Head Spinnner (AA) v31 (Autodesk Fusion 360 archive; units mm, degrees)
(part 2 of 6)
sketch "Driven Gear Hole for Z Restric." plane through (0, 0, 31.75) normal (0, 0, -1) x axis (1, 0, 0)
  line L1 (10.4441, 8.6506) -> (10.3664, 8.5861)
  curve K1 (11.5764, 10.8628) -> (10.4441, 8.6506)
  curve K2 (10.8676, 11.5719) -> (8.655, 10.4405)
  line L2 (8.5904, 10.3628) -> (8.655, 10.4405)
  line L3 (7.2598, 11.4546) -> (7.2058, 11.3693)
  curve K3 (7.6531, 13.9084) -> (7.2598, 11.4546)
  curve K4 (6.7598, 14.3638) -> (5.0051, 12.604)
  line L4 (4.9677, 12.5102) -> (5.0051, 12.604)
  line L5 (3.3648, 13.1374) -> (3.3398, 13.0395)
  curve K5 (2.9806, 15.5926) -> (3.3648, 13.1374)
  curve K6 (1.9903, 15.7497) -> (0.8652, 13.5338)
  line L6 (0.8587, 13.433) -> (0.8652, 13.5338)
  line L7 (-0.8596, 13.5342) -> (-0.8531, 13.4334)
  curve K7 (-1.9837, 15.7505) -> (-0.8596, 13.5342)
  curve K8 (-2.9741, 15.5939) -> (-3.3593, 13.1388)
  line L8 (-3.3344, 13.0409) -> (-3.3593, 13.1388)
  line L9 (-4.9998, 12.6061) -> (-4.9625, 12.5123)
  curve K9 (-6.7538, 14.3666) -> (-4.9998, 12.6061)
  curve K10 (-7.6473, 13.9116) -> (-7.255, 11.4576)
  line L10 (-7.201, 11.3723) -> (-7.255, 11.4576)
  line L11 (-8.6506, 10.4441) -> (-8.5861, 10.3664)
  curve K11 (-10.8628, 11.5764) -> (-8.6506, 10.4441)
  curve K12 (-11.5719, 10.8676) -> (-10.4405, 8.655)
  line L12 (-10.3628, 8.5904) -> (-10.4405, 8.655)
  line L13 (-11.4546, 7.2598) -> (-11.3693, 7.2058)
  curve K13 (-13.9084, 7.6531) -> (-11.4546, 7.2598)
  curve K14 (-14.3638, 6.7598) -> (-12.604, 5.0051)
  line L14 (-12.5102, 4.9677) -> (-12.604, 5.0051)
  line L15 (-13.1374, 3.3648) -> (-13.0395, 3.3398)
  curve K15 (-15.5926, 2.9806) -> (-13.1374, 3.3648)
  curve K16 (-15.7497, 1.9903) -> (-13.5338, 0.8652)
  line L16 (-13.433, 0.8587) -> (-13.5338, 0.8652)
  line L17 (-13.5342, -0.8596) -> (-13.4334, -0.8531)
  curve K17 (-15.7505, -1.9837) -> (-13.5342, -0.8596)
  curve K18 (-15.5939, -2.9741) -> (-13.1388, -3.3593)
  line L18 (-13.0409, -3.3344) -> (-13.1388, -3.3593)
  line L19 (-12.6061, -4.9998) -> (-12.5123, -4.9625)
  curve K19 (-14.3666, -6.7538) -> (-12.6061, -4.9998)
  curve K20 (-13.9116, -7.6473) -> (-11.4576, -7.255)
  line L20 (-11.3723, -7.201) -> (-11.4576, -7.255)
  line L21 (-10.4441, -8.6506) -> (-10.3664, -8.5861)
  curve K21 (-11.5764, -10.8628) -> (-10.4441, -8.6506)
  curve K22 (-10.8676, -11.5719) -> (-8.655, -10.4405)
  line L22 (-8.5904, -10.3628) -> (-8.655, -10.4405)
  line L23 (-7.2598, -11.4546) -> (-7.2058, -11.3693)
  curve K23 (-7.6531, -13.9084) -> (-7.2598, -11.4546)
  curve K24 (-6.7598, -14.3638) -> (-5.0051, -12.604)
  line L24 (-4.9677, -12.5102) -> (-5.0051, -12.604)
  line L25 (-3.3648, -13.1374) -> (-3.3398, -13.0395)
  curve K25 (-2.9806, -15.5926) -> (-3.3648, -13.1374)
  curve K26 (-1.9903, -15.7497) -> (-0.8652, -13.5338)
  line L26 (-0.8587, -13.433) -> (-0.8652, -13.5338)
  line L27 (0.8596, -13.5342) -> (0.8531, -13.4334)
  curve K27 (1.9837, -15.7505) -> (0.8596, -13.5342)
  curve K28 (2.9741, -15.5939) -> (3.3593, -13.1388)
  line L28 (3.3344, -13.0409) -> (3.3593, -13.1388)
  line L29 (4.9998, -12.6061) -> (4.9625, -12.5123)
  curve K29 (6.7538, -14.3666) -> (4.9998, -12.6061)
  curve K30 (7.6473, -13.9116) -> (7.255, -11.4576)
  line L30 (7.201, -11.3723) -> (7.255, -11.4576)
  line L31 (8.6506, -10.4441) -> (8.5861, -10.3664)
  curve K31 (10.8628, -11.5764) -> (8.6506, -10.4441)
  curve K32 (11.5719, -10.8676) -> (10.4405, -8.655)
  line L32 (10.3628, -8.5904) -> (10.4405, -8.655)
  line L33 (11.4546, -7.2598) -> (11.3693, -7.2058)
  curve K33 (13.9084, -7.6531) -> (11.4546, -7.2598)
  curve K34 (14.3638, -6.7598) -> (12.604, -5.0051)
  line L34 (12.5102, -4.9677) -> (12.604, -5.0051)
  line L35 (13.1374, -3.3648) -> (13.0395, -3.3398)
  curve K35 (15.5926, -2.9806) -> (13.1374, -3.3648)
  curve K36 (15.7497, -1.9903) -> (13.5338, -0.8652)
  line L36 (13.433, -0.8587) -> (13.5338, -0.8652)
  line L37 (13.5342, 0.8596) -> (13.4334, 0.8531)
  curve K37 (15.7505, 1.9837) -> (13.5342, 0.8596)
  curve K38 (15.5939, 2.9741) -> (13.1388, 3.3593)
  line L38 (13.0409, 3.3344) -> (13.1388, 3.3593)
  line L39 (12.6061, 4.9998) -> (12.5123, 4.9625)
  curve K39 (14.3666, 6.7538) -> (12.6061, 4.9998)
  curve K40 (13.9116, 7.6473) -> (11.4576, 7.255)
  line L40 (11.3723, 7.201) -> (11.4576, 7.255)
  circle C1 centre (0, 0) radius 3.175
  arc A1 centre (10.9017, 7.9411) radius 0.8382 clockwise from (10.2242, 7.4476) to (10.3664, 8.5861)
  arc A2 centre (0, 0) radius 15.8749 clockwise from (10.8676, 11.5719) to (11.5764, 10.8628)
  arc A3 centre (7.9457, 10.8984) radius 0.8382 clockwise from (8.5904, 10.3628) to (7.4519, 10.2211)
  arc A4 centre (0, 0) radius 12.6492 clockwise from (7.4224, 10.2425) to (7.4519, 10.2211)
  arc A5 centre (7.9142, 10.9213) radius 0.8382 clockwise from (7.4224, 10.2425) to (7.2058, 11.3693)
  arc A6 centre (0, 0) radius 15.8749 clockwise from (6.7598, 14.3638) to (7.6531, 13.9084)
  arc A7 centre (4.189, 12.8204) radius 0.8382 clockwise from (4.9677, 12.5102) to (3.9286, 12.0236)
  arc A8 centre (0, 0) radius 12.6492 clockwise from (3.894, 12.0349) to (3.9286, 12.0236)
  arc A9 centre (4.152, 12.8324) radius 0.8382 clockwise from (3.894, 12.0349) to (3.3398, 13.0395)
  arc A10 centre (0, 0) radius 15.8749 clockwise from (1.9903, 15.7497) to (2.9806, 15.5926)
  arc A11 centre (0.0222, 13.4873) radius 0.8382 clockwise from (0.8587, 13.433) to (0.0209, 12.6491)
  arc A12 centre (0, 0) radius 12.6492 clockwise from (-0.0156, 12.6491) to (0.0209, 12.6491)
  arc A13 centre (-0.0166, 13.4873) radius 0.8382 clockwise from (-0.0156, 12.6491) to (-0.8531, 13.4334)
  arc A14 centre (0, 0) radius 15.8749 clockwise from (-2.9741, 15.5939) to (-1.9837, 15.7505)
  arc A15 centre (-4.1467, 12.8341) radius 0.8382 clockwise from (-3.3344, 13.0409) to (-3.889, 12.0365)
  arc A16 centre (0, 0) radius 12.6492 clockwise from (-3.9236, 12.0252) to (-3.889, 12.0365)
  arc A17 centre (-4.1836, 12.8221) radius 0.8382 clockwise from (-3.9236, 12.0252) to (-4.9625, 12.5123)
  arc A18 centre (0, 0) radius 15.8749 clockwise from (-7.6473, 13.9116) to (-6.7538, 14.3666)
  arc A19 centre (-7.9097, 10.9246) radius 0.8382 clockwise from (-7.201, 11.3723) to (-7.4181, 10.2456)
  arc A20 centre (0, 0) radius 12.6492 clockwise from (-7.4476, 10.2242) to (-7.4181, 10.2456)
  arc A21 centre (-7.9411, 10.9017) radius 0.8382 clockwise from (-7.4476, 10.2242) to (-8.5861, 10.3664)
  arc A22 centre (0, 0) radius 15.8749 clockwise from (-11.5719, 10.8676) to (-10.8628, 11.5764)
  arc A23 centre (-10.8984, 7.9457) radius 0.8382 clockwise from (-10.3628, 8.5904) to (-10.2211, 7.4519)
  arc A24 centre (0, 0) radius 12.6492 clockwise from (-10.2425, 7.4224) to (-10.2211, 7.4519)
  arc A25 centre (-10.9213, 7.9142) radius 0.8382 clockwise from (-10.2425, 7.4224) to (-11.3693, 7.2058)
  arc A26 centre (0, 0) radius 15.8749 clockwise from (-14.3638, 6.7598) to (-13.9084, 7.6531)
  arc A27 centre (-12.8204, 4.189) radius 0.8382 clockwise from (-12.5102, 4.9677) to (-12.0236, 3.9286)
  arc A28 centre (0, 0) radius 12.6492 clockwise from (-12.0349, 3.894) to (-12.0236, 3.9286)
  arc A29 centre (-12.8324, 4.152) radius 0.8382 clockwise from (-12.0349, 3.894) to (-13.0395, 3.3398)
  arc A30 centre (0, 0) radius 15.8749 clockwise from (-15.7497, 1.9903) to (-15.5926, 2.9806)
  arc A31 centre (-13.4873, 0.0222) radius 0.8382 clockwise from (-13.433, 0.8587) to (-12.6491, 0.0209)
  arc A32 centre (0, 0) radius 12.6492 clockwise from (-12.6491, -0.0156) to (-12.6491, 0.0209)
  arc A33 centre (-13.4873, -0.0166) radius 0.8382 clockwise from (-12.6491, -0.0156) to (-13.4334, -0.8531)
  arc A34 centre (0, 0) radius 15.8749 clockwise from (-15.5939, -2.9741) to (-15.7505, -1.9837)
  arc A35 centre (-12.8341, -4.1467) radius 0.8382 clockwise from (-13.0409, -3.3344) to (-12.0365, -3.889)
  arc A36 centre (0, 0) radius 12.6492 clockwise from (-12.0252, -3.9236) to (-12.0365, -3.889)
  arc A37 centre (-12.8221, -4.1836) radius 0.8382 clockwise from (-12.0252, -3.9236) to (-12.5123, -4.9625)
  arc A38 centre (0, 0) radius 15.8749 clockwise from (-13.9116, -7.6473) to (-14.3666, -6.7538)
  arc A39 centre (-10.9246, -7.9097) radius 0.8382 clockwise from (-11.3723, -7.201) to (-10.2456, -7.4181)
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  dimension "d185" diameter = 2.9
extrude "Extrude3" add sketch "Driven Gear Hole for Z Restric." against normal blind 25.4
chamfer "Chamfer1" distance 0.635
copy_paste "CutPaste1"
copy_paste "CutPaste1"
copy_paste "CutPaste2"
copy_paste "CutPaste3"
copy_paste "CutPaste1"
copy_paste "CutPaste2"
component_from_bodies "Body->Comp1"
copy_paste "CutPaste2"
sketch "Sketch73" plane through (0, 0, 60.325) normal (0, 0, -1) x axis (1, 0, 0)
  line L1 (6.35, 41.6831) -> (6.35, 50.6576)
  line L2 (47.0457, -19.8295) -> (39.2736, -15.3423)
  line L3 (32.9236, -26.3408) -> (40.6957, -30.828)
  line L4 (-40.6957, -30.828) -> (-32.9236, -26.3408)
  line L5 (-39.2736, -15.3423) -> (-47.0457, -19.8295)
  line L6 (-6.35, 50.6576) -> (-6.35, 41.6831)
  line L7 (0, -46.1703) -> (0, 0)
  line L8 (-1.905, -44.9003) -> (1.905, -44.9003)
  line L9 (-1.905, -47.4403) -> (-1.905, -44.9003)
  line L10 (1.905, -47.4403) -> (-1.905, -47.4403)
  line L11 (1.905, -44.9003) -> (1.905, -47.4403)
  line L12 (-1.905, -47.4403) -> (1.905, -44.9003)
  line L13 (1.905, -47.4403) -> (-1.905, -44.9003)
  line L14 (2.032, -47.5673) -> (-2.032, -47.5673)
  line L15 (2.032, -44.7733) -> (2.032, -47.5673)
  line L16 (-2.032, -44.7733) -> (2.032, -44.7733)
  line L17 (-2.032, -47.5673) -> (-2.032, -44.7733)
  line L18 (42.2105, 22.0239) -> (39.7908, 20.6269)
  line L19 (42.037, 22.0704) -> (39.8373, 20.8004)
  line L20 (40.132, 25.3699) -> (42.037, 22.0704)
  line L21 (40.1785, 25.5434) -> (42.2105, 22.0239)
  line L22 (37.9323, 24.0999) -> (40.132, 25.3699)
  line L23 (37.7588, 24.1464) -> (40.1785, 25.5434)
  line L24 (39.7908, 20.6269) -> (37.7588, 24.1464)
  line L25 (39.8373, 20.8004) -> (37.9323, 24.0999)
  line L26 (-40.1785, 25.5434) -> (-37.7588, 24.1464)
  line L27 (-40.132, 25.3699) -> (-37.9323, 24.0999)
  line L28 (-42.037, 22.0704) -> (-40.132, 25.3699)
  line L29 (-42.2105, 22.0239) -> (-40.1785, 25.5434)
  line L30 (-39.8373, 20.8004) -> (-42.037, 22.0704)
  line L31 (-39.7908, 20.6269) -> (-42.2105, 22.0239)
  line L32 (-37.7588, 24.1464) -> (-39.7908, 20.6269)
  line L33 (-37.9323, 24.0999) -> (-39.8373, 20.8004)
  arc A1 centre (0, 0) radius 42.164 clockwise from (6.35, 41.6831) to (39.2736, -15.3423)
  arc A2 centre (0, 0) radius 51.054 clockwise from (47.0457, -19.8295) to (40.6957, -30.828)
  arc A3 centre (0, 0) radius 42.164 clockwise from (32.9236, -26.3408) to (-32.9236, -26.3408)
  arc A4 centre (0, 0) radius 51.054 clockwise from (-40.6957, -30.828) to (-47.0457, -19.8295)
  arc A5 centre (0, 0) radius 42.164 clockwise from (-39.2736, -15.3423) to (-6.35, 41.6831)
  arc A6 centre (0, 0) radius 51.054 clockwise from (-6.35, 50.6576) to (6.35, 50.6576)
  circle C1 centre (0, 0) radius 85.725
  circle C2 centre (0, 0) radius 16.0443
  circle C3 centre (0, 46.1703) radius 1.881
  circle C4 centre (-39.9847, -23.0852) radius 1.881
  circle C5 centre (39.9847, -23.0852) radius 1.881
  circle C6 centre (0, 0) radius 51.054
  circle C7 centre (0, 0) radius 46.1703
  point P17 (-39.9847, -23.0852)
  point P19 (0, 0)
  point P20 (0, 0)
  point P26 (0, -46.1703)
  point P21 (0, -46.1703)
  point P22 (1.905, -44.9003)
  point P23 (-1.905, -44.9003)
  point P25 (1.905, -47.4403)
  concentric C2 C7
  coincident P17 C7
  coincident P19 P20
  vertical L7
  horizontal L8
  perpendicular L8 L9
  parallel L8 L10
  parallel L9 L11
  coincident L12 P26
  coincident L13 P26
  coincident P21 P26
  coincident C7 P26
  dimension "d622" distance P22 P23 = 3.81
  dimension "d623" distance P22 P25 = 2.54
  dimension "d624" = 0.127 (= "clearance / 2")
  dimension "d626" C-Pattern1-Angle = 360
extrude "Extrude8" cut sketch "Sketch73" profile of L8 L9 L10 L11 L17 L16 L15 L14 L18 L19 L20 L21 L22 L23 L24 L25 L26 L27 L28 L29 L30 L31 L32 L33 along normal blind 15.24
extrude "Extrude9" add sketch "Sketch73" profile of L8 L9 L10 L11 L19 L20 L22 L25 L27 L28 L30 L33 along normal blind 8.255
chamfer "Chamfer1" distance 0.8255
sketch "Fill Top of Driven Gear" plane through (0, 0, -3.175) normal (0, 0, -1) x axis (1, 0, 0)
  line L1 (13.5023, 1.2654) -> (13.4017, 1.2561)
  curve K1 (15.867, 0.5013) -> (13.5023, 1.2654)
  curve K2 (13.5023, -1.2654) -> (15.867, -0.5013)
  line L2 (13.4017, -1.2561) -> (13.5023, -1.2654)
  line L3 (13.2324, -2.969) -> (13.1339, -2.9468)
  curve K3 (15.2454, -4.4264) -> (13.2324, -2.969)
  curve K4 (12.4504, -5.3759) -> (14.9355, -5.38)
  line L4 (12.3576, -5.3359) -> (12.4504, -5.3759)
  line L5 (11.6673, -6.9127) -> (11.5805, -6.8611)
  curve K5 (13.1314, -8.9208) -> (11.6673, -6.9127)
  curve K6 (10.1798, -8.9602) -> (12.542, -9.732)
  line L6 (10.1039, -8.8935) -> (10.1798, -8.9602)
  line L7 (8.9602, -10.1798) -> (8.8935, -10.1039)
  curve K7 (9.732, -12.542) -> (8.9602, -10.1798)
  curve K8 (6.9127, -11.6673) -> (8.9208, -13.1314)
  line L8 (6.8611, -11.5805) -> (6.9127, -11.6673)
  line L9 (5.3759, -12.4504) -> (5.3359, -12.3576)
  curve K9 (5.38, -14.9355) -> (5.3759, -12.4504)
  curve K10 (2.969, -13.2324) -> (4.4264, -15.2454)
  line L10 (2.9468, -13.1339) -> (2.969, -13.2324)
  line L11 (1.2654, -13.5023) -> (1.2561, -13.4017)
  curve K11 (0.5013, -15.867) -> (1.2654, -13.5023)
  curve K12 (-1.2654, -13.5023) -> (-0.5013, -15.867)
  line L12 (-1.2561, -13.4017) -> (-1.2654, -13.5023)
  line L13 (-2.969, -13.2324) -> (-2.9468, -13.1339)
  curve K13 (-4.4264, -15.2454) -> (-2.969, -13.2324)
  curve K14 (-5.3759, -12.4504) -> (-5.38, -14.9355)
  line L14 (-5.3359, -12.3576) -> (-5.3759, -12.4504)
  line L15 (-6.9127, -11.6673) -> (-6.8611, -11.5805)
  curve K15 (-8.9208, -13.1314) -> (-6.9127, -11.6673)
  curve K16 (-8.9602, -10.1798) -> (-9.732, -12.542)
  line L16 (-8.8935, -10.1039) -> (-8.9602, -10.1798)
  line L17 (-10.1798, -8.9602) -> (-10.1039, -8.8935)
  curve K17 (-12.542, -9.732) -> (-10.1798, -8.9602)
  curve K18 (-11.6673, -6.9127) -> (-13.1314, -8.9208)
  line L18 (-11.5805, -6.8611) -> (-11.6673, -6.9127)
  line L19 (-12.4504, -5.3759) -> (-12.3576, -5.3359)
  curve K19 (-14.9355, -5.38) -> (-12.4504, -5.3759)
  curve K20 (-13.2324, -2.969) -> (-15.2454, -4.4264)
  line L20 (-13.1339, -2.9468) -> (-13.2324, -2.969)
  line L21 (-13.5023, -1.2654) -> (-13.4017, -1.2561)
  curve K21 (-15.867, -0.5013) -> (-13.5023, -1.2654)
  curve K22 (-13.5023, 1.2654) -> (-15.867, 0.5013)
  line L22 (-13.4017, 1.2561) -> (-13.5023, 1.2654)
  line L23 (-13.2324, 2.969) -> (-13.1339, 2.9468)
  curve K23 (-15.2454, 4.4264) -> (-13.2324, 2.969)
  curve K24 (-12.4504, 5.3759) -> (-14.9355, 5.38)
  line L24 (-12.3576, 5.3359) -> (-12.4504, 5.3759)
  line L25 (-11.6673, 6.9127) -> (-11.5805, 6.8611)
  curve K25 (-13.1314, 8.9208) -> (-11.6673, 6.9127)
  curve K26 (-10.1798, 8.9602) -> (-12.542, 9.732)
  line L26 (-10.1039, 8.8935) -> (-10.1798, 8.9602)
  line L27 (-8.9602, 10.1798) -> (-8.8935, 10.1039)
  curve K27 (-9.732, 12.542) -> (-8.9602, 10.1798)
  curve K28 (-6.9127, 11.6673) -> (-8.9208, 13.1314)
  line L28 (-6.8611, 11.5805) -> (-6.9127, 11.6673)
  line L29 (-5.3759, 12.4504) -> (-5.3359, 12.3576)
  curve K29 (-5.38, 14.9355) -> (-5.3759, 12.4504)
  curve K30 (-2.969, 13.2324) -> (-4.4264, 15.2454)
  line L30 (-2.9468, 13.1339) -> (-2.969, 13.2324)
  line L31 (-1.2654, 13.5023) -> (-1.2561, 13.4017)
  curve K31 (-0.5013, 15.867) -> (-1.2654, 13.5023)
  curve K32 (1.2654, 13.5023) -> (0.5013, 15.867)
  line L32 (1.2561, 13.4017) -> (1.2654, 13.5023)
  line L33 (2.969, 13.2324) -> (2.9468, 13.1339)
  curve K33 (4.4264, 15.2454) -> (2.969, 13.2324)
  curve K34 (5.3759, 12.4504) -> (5.38, 14.9355)
  line L34 (5.3359, 12.3576) -> (5.3759, 12.4504)
  line L35 (6.9127, 11.6673) -> (6.8611, 11.5805)
  curve K35 (8.9208, 13.1314) -> (6.9127, 11.6673)
  curve K36 (8.9602, 10.1798) -> (9.732, 12.542)
  line L36 (8.8935, 10.1039) -> (8.9602, 10.1798)
  line L37 (10.1798, 8.9602) -> (10.1039, 8.8935)
  curve K37 (12.542, 9.732) -> (10.1798, 8.9602)
  curve K38 (11.6673, 6.9127) -> (13.1314, 8.9208)
  line L38 (11.5805, 6.8611) -> (11.6673, 6.9127)
  line L39 (12.4504, 5.3759) -> (12.3576, 5.3359)
  curve K39 (14.9355, 5.38) -> (12.4504, 5.3759)
  curve K40 (13.2324, 2.969) -> (15.2454, 4.4264)
  line L40 (13.1339, 2.9468) -> (13.2324, 2.969)
  arc A1 centre (13.3243, 2.0907) radius 0.8382 clockwise from (13.4017, 1.2561) to (12.4963, 1.9608)
  arc A2 centre (0, 0) radius 15.8749 clockwise from (15.867, 0.5013) to (15.867, -0.5013)
  arc A3 centre (13.3243, -2.0907) radius 0.8382 clockwise from (12.4963, -1.9608) to (13.4017, -1.2561)
  arc A4 centre (0, 0) radius 12.6492 clockwise from (12.4963, -1.9608) to (12.4906, -1.9968)
  arc A5 centre (13.3183, -2.1291) radius 0.8382 clockwise from (13.1339, -2.9468) to (12.4906, -1.9968)
  arc A6 centre (0, 0) radius 15.8749 clockwise from (15.2454, -4.4264) to (14.9355, -5.38)
  arc A7 centre (12.0261, -6.1058) radius 0.8382 clockwise from (11.2787, -5.7264) to (12.3576, -5.3359)
  arc A8 centre (0, 0) radius 12.6492 clockwise from (11.2787, -5.7264) to (11.2622, -5.7588)
  arc A9 centre (12.0085, -6.1404) radius 0.8382 clockwise from (11.5805, -6.8611) to (11.2622, -5.7588)
  arc A10 centre (0, 0) radius 15.8749 clockwise from (13.1314, -8.9208) to (12.542, -9.732)
  arc A11 centre (9.5507, -9.5233) radius 0.8382 clockwise from (8.9572, -8.9314) to (10.1039, -8.8935)
  arc A12 centre (0, 0) radius 12.6492 clockwise from (8.9572, -8.9314) to (8.9314, -8.9572)
  arc A13 centre (9.5233, -9.5507) radius 0.8382 clockwise from (8.8935, -10.1039) to (8.9314, -8.9572)
  arc A14 centre (0, 0) radius 15.8749 clockwise from (9.732, -12.542) to (8.9208, -13.1314)
  arc A15 centre (6.1404, -12.0085) radius 0.8382 clockwise from (5.7588, -11.2622) to (6.8611, -11.5805)
  arc A16 centre (0, 0) radius 12.6492 clockwise from (5.7588, -11.2622) to (5.7264, -11.2787)
  arc A17 centre (6.1058, -12.0261) radius 0.8382 clockwise from (5.3359, -12.3576) to (5.7264, -11.2787)
  arc A18 centre (0, 0) radius 15.8749 clockwise from (5.38, -14.9355) to (4.4264, -15.2454)
  arc A19 centre (2.1291, -13.3183) radius 0.8382 clockwise from (1.9968, -12.4906) to (2.9468, -13.1339)
  arc A20 centre (0, 0) radius 12.6492 clockwise from (1.9968, -12.4906) to (1.9608, -12.4963)
  arc A21 centre (2.0907, -13.3243) radius 0.8382 clockwise from (1.2561, -13.4017) to (1.9608, -12.4963)
  arc A22 centre (0, 0) radius 15.8749 clockwise from (0.5013, -15.867) to (-0.5013, -15.867)
  arc A23 centre (-2.0907, -13.3243) radius 0.8382 clockwise from (-1.9608, -12.4963) to (-1.2561, -13.4017)
  arc A24 centre (0, 0) radius 12.6492 clockwise from (-1.9608, -12.4963) to (-1.9968, -12.4906)
  arc A25 centre (-2.1291, -13.3183) radius 0.8382 clockwise from (-2.9468, -13.1339) to (-1.9968, -12.4906)
  arc A26 centre (0, 0) radius 15.8749 clockwise from (-4.4264, -15.2454) to (-5.38, -14.9355)
  arc A27 centre (-6.1058, -12.0261) radius 0.8382 clockwise from (-5.7264, -11.2787) to (-5.3359, -12.3576)
  arc A28 centre (0, 0) radius 12.6492 clockwise from (-5.7264, -11.2787) to (-5.7588, -11.2622)
  arc A29 centre (-6.1404, -12.0085) radius 0.8382 clockwise from (-6.8611, -11.5805) to (-5.7588, -11.2622)
  arc A30 centre (0, 0) radius 15.8749 clockwise from (-8.9208, -13.1314) to (-9.732, -12.542)
  arc A31 centre (-9.5233, -9.5507) radius 0.8382 clockwise from (-8.9314, -8.9572) to (-8.8935, -10.1039)
  arc A32 centre (0, 0) radius 12.6492 clockwise from (-8.9314, -8.9572) to (-8.9572, -8.9314)
  arc A33 centre (-9.5507, -9.5233) radius 0.8382 clockwise from (-10.1039, -8.8935) to (-8.9572, -8.9314)
  arc A34 centre (0, 0) radius 15.8749 clockwise from (-12.542, -9.732) to (-13.1314, -8.9208)
  arc A35 centre (-12.0085, -6.1404) radius 0.8382 clockwise from (-11.2622, -5.7588) to (-11.5805, -6.8611)
  arc A36 centre (0, 0) radius 12.6492 clockwise from (-11.2622, -5.7588) to (-11.2787, -5.7264)
  arc A37 centre (-12.0261, -6.1058) radius 0.8382 clockwise from (-12.3576, -5.3359) to (-11.2787, -5.7264)
  arc A38 centre (0, 0) radius 15.8749 clockwise from (-14.9355, -5.38) to (-15.2454, -4.4264)
  arc A39 centre (-13.3183, -2.1291) radius 0.8382 clockwise from (-12.4906, -1.9968) to (-13.1339, -2.9468)
  arc A40 centre (0, 0) radius 12.6492 clockwise from (-12.4906, -1.9968) to (-12.4963, -1.9608)
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  dimension "d163" diameter = 31.877
sketch "Driven Gear OD" plane through (0, 0, 57.15) normal (0, 0, -1) x axis (1, 0, 0)
  line L1 (13.1388, 3.3593) -> (13.0409, 3.3344)
  curve K1 (15.5939, 2.9741) -> (13.1388, 3.3593)
  curve K2 (13.5342, 0.8596) -> (15.7505, 1.9837)
  line L2 (13.4334, 0.8531) -> (13.5342, 0.8596)
  line L3 (13.5338, -0.8652) -> (13.433, -0.8587)
  curve K3 (15.7497, -1.9903) -> (13.5338, -0.8652)
  curve K4 (13.1374, -3.3648) -> (15.5926, -2.9806)
  line L4 (13.0395, -3.3398) -> (13.1374, -3.3648)
  line L5 (12.604, -5.0051) -> (12.5102, -4.9677)
  curve K5 (14.3638, -6.7598) -> (12.604, -5.0051)
  curve K6 (11.4546, -7.2598) -> (13.9084, -7.6531)
  line L6 (11.3693, -7.2058) -> (11.4546, -7.2598)
  line L7 (10.4405, -8.655) -> (10.3628, -8.5904)
  curve K7 (11.5719, -10.8676) -> (10.4405, -8.655)
  curve K8 (8.6506, -10.4441) -> (10.8628, -11.5764)
  line L8 (8.5861, -10.3664) -> (8.6506, -10.4441)
  line L9 (7.255, -11.4576) -> (7.201, -11.3723)
  curve K9 (7.6473, -13.9116) -> (7.255, -11.4576)
  curve K10 (4.9998, -12.6061) -> (6.7538, -14.3666)
  line L10 (4.9625, -12.5123) -> (4.9998, -12.6061)
  line L11 (3.3593, -13.1388) -> (3.3344, -13.0409)
  curve K11 (2.9741, -15.5939) -> (3.3593, -13.1388)
  curve K12 (0.8596, -13.5342) -> (1.9837, -15.7505)
  line L12 (0.8531, -13.4334) -> (0.8596, -13.5342)
  line L13 (-0.8652, -13.5338) -> (-0.8587, -13.433)
  curve K13 (-1.9903, -15.7497) -> (-0.8652, -13.5338)
  curve K14 (-3.3648, -13.1374) -> (-2.9806, -15.5926)
  line L14 (-3.3398, -13.0395) -> (-3.3648, -13.1374)
  line L15 (-5.0051, -12.604) -> (-4.9677, -12.5102)
  curve K15 (-6.7598, -14.3638) -> (-5.0051, -12.604)
  curve K16 (-7.2598, -11.4546) -> (-7.6531, -13.9084)
  line L16 (-7.2058, -11.3693) -> (-7.2598, -11.4546)
  line L17 (-8.655, -10.4405) -> (-8.5904, -10.3628)
  curve K17 (-10.8676, -11.5719) -> (-8.655, -10.4405)
  curve K18 (-10.4441, -8.6506) -> (-11.5764, -10.8628)
  line L18 (-10.3664, -8.5861) -> (-10.4441, -8.6506)
  line L19 (-11.4576, -7.255) -> (-11.3723, -7.201)
  curve K19 (-13.9116, -7.6473) -> (-11.4576, -7.255)
  curve K20 (-12.6061, -4.9998) -> (-14.3666, -6.7538)
  line L20 (-12.5123, -4.9625) -> (-12.6061, -4.9998)
  line L21 (-13.1388, -3.3593) -> (-13.0409, -3.3344)
  curve K21 (-15.5939, -2.9741) -> (-13.1388, -3.3593)
  curve K22 (-13.5342, -0.8596) -> (-15.7505, -1.9837)
  line L22 (-13.4334, -0.8531) -> (-13.5342, -0.8596)
  line L23 (-13.5338, 0.8652) -> (-13.433, 0.8587)
  curve K23 (-15.7497, 1.9903) -> (-13.5338, 0.8652)
  curve K24 (-13.1374, 3.3648) -> (-15.5926, 2.9806)
  line L24 (-13.0395, 3.3398) -> (-13.1374, 3.3648)
  line L25 (-12.604, 5.0051) -> (-12.5102, 4.9677)
  curve K25 (-14.3638, 6.7598) -> (-12.604, 5.0051)
  curve K26 (-11.4546, 7.2598) -> (-13.9084, 7.6531)
  line L26 (-11.3693, 7.2058) -> (-11.4546, 7.2598)
  line L27 (-10.4405, 8.655) -> (-10.3628, 8.5904)
  curve K27 (-11.5719, 10.8676) -> (-10.4405, 8.655)
  curve K28 (-8.6506, 10.4441) -> (-10.8628, 11.5764)
  line L28 (-8.5861, 10.3664) -> (-8.6506, 10.4441)
  line L29 (-7.255, 11.4576) -> (-7.201, 11.3723)
  curve K29 (-7.6473, 13.9116) -> (-7.255, 11.4576)
  curve K30 (-4.9998, 12.6061) -> (-6.7538, 14.3666)
  line L30 (-4.9625, 12.5123) -> (-4.9998, 12.6061)
  line L31 (-3.3593, 13.1388) -> (-3.3344, 13.0409)
  curve K31 (-2.9741, 15.5939) -> (-3.3593, 13.1388)
  curve K32 (-0.8596, 13.5342) -> (-1.9837, 15.7505)
  line L32 (-0.8531, 13.4334) -> (-0.8596, 13.5342)
  line L33 (0.8652, 13.5338) -> (0.8587, 13.433)
  curve K33 (1.9903, 15.7497) -> (0.8652, 13.5338)
  curve K34 (3.3648, 13.1374) -> (2.9806, 15.5926)
  line L34 (3.3398, 13.0395) -> (3.3648, 13.1374)
  line L35 (5.0051, 12.604) -> (4.9677, 12.5102)
  curve K35 (6.7598, 14.3638) -> (5.0051, 12.604)
  curve K36 (7.2598, 11.4546) -> (7.6531, 13.9084)
  line L36 (7.2058, 11.3693) -> (7.2598, 11.4546)
  line L37 (8.655, 10.4405) -> (8.5904, 10.3628)
  curve K37 (10.8676, 11.5719) -> (8.655, 10.4405)
  curve K38 (10.4441, 8.6506) -> (11.5764, 10.8628)
  line L38 (10.3664, 8.5861) -> (10.4441, 8.6506)
  line L39 (11.4576, 7.255) -> (11.3723, 7.201)
  curve K39 (13.9116, 7.6473) -> (11.4576, 7.255)
  curve K40 (12.6061, 4.9998) -> (14.3666, 6.7538)
  line L40 (12.5123, 4.9625) -> (12.6061, 4.9998)
  arc A1 centre (12.8341, 4.1467) radius 0.8382 clockwise from (13.0409, 3.3344) to (12.0365, 3.889)
  arc A2 centre (0, 0) radius 15.8749 clockwise from (15.5939, 2.9741) to (15.7505, 1.9837)
  arc A3 centre (13.4873, 0.0166) radius 0.8382 clockwise from (12.6491, 0.0156) to (13.4334, 0.8531)
  arc A4 centre (0, 0) radius 12.6492 clockwise from (12.6491, 0.0156) to (12.6491, -0.0209)
  arc A5 centre (13.4873, -0.0222) radius 0.8382 clockwise from (13.433, -0.8587) to (12.6491, -0.0209)
  arc A6 centre (0, 0) radius 15.8749 clockwise from (15.7497, -1.9903) to (15.5926, -2.9806)
  arc A7 centre (12.8324, -4.152) radius 0.8382 clockwise from (12.0349, -3.894) to (13.0395, -3.3398)
  arc A8 centre (0, 0) radius 12.6492 clockwise from (12.0349, -3.894) to (12.0236, -3.9286)
  arc A9 centre (12.8204, -4.189) radius 0.8382 clockwise from (12.5102, -4.9677) to (12.0236, -3.9286)
  arc A10 centre (0, 0) radius 15.8749 clockwise from (14.3638, -6.7598) to (13.9084, -7.6531)
  arc A11 centre (10.9213, -7.9142) radius 0.8382 clockwise from (10.2425, -7.4224) to (11.3693, -7.2058)
  arc A12 centre (0, 0) radius 12.6492 clockwise from (10.2425, -7.4224) to (10.2211, -7.4519)
  arc A13 centre (10.8984, -7.9457) radius 0.8382 clockwise from (10.3628, -8.5904) to (10.2211, -7.4519)
  arc A14 centre (0, 0) radius 15.8749 clockwise from (11.5719, -10.8676) to (10.8628, -11.5764)
  arc A15 centre (7.9411, -10.9017) radius 0.8382 clockwise from (7.4476, -10.2242) to (8.5861, -10.3664)
  arc A16 centre (0, 0) radius 12.6492 clockwise from (7.4476, -10.2242) to (7.4181, -10.2456)
  arc A17 centre (7.9097, -10.9246) radius 0.8382 clockwise from (7.201, -11.3723) to (7.4181, -10.2456)
  arc A18 centre (0, 0) radius 15.8749 clockwise from (7.6473, -13.9116) to (6.7538, -14.3666)
  arc A19 centre (4.1836, -12.8221) radius 0.8382 clockwise from (3.9236, -12.0252) to (4.9625, -12.5123)
  arc A20 centre (0, 0) radius 12.6492 clockwise from (3.9236, -12.0252) to (3.889, -12.0365)
  arc A21 centre (4.1467, -12.8341) radius 0.8382 clockwise from (3.3344, -13.0409) to (3.889, -12.0365)
  arc A22 centre (0, 0) radius 15.8749 clockwise from (2.9741, -15.5939) to (1.9837, -15.7505)
  arc A23 centre (0.0166, -13.4873) radius 0.8382 clockwise from (0.0156, -12.6491) to (0.8531, -13.4334)
  arc A24 centre (0, 0) radius 12.6492 clockwise from (0.0156, -12.6491) to (-0.0209, -12.6491)
  arc A25 centre (-0.0222, -13.4873) radius 0.8382 clockwise from (-0.8587, -13.433) to (-0.0209, -12.6491)
  arc A26 centre (0, 0) radius 15.8749 clockwise from (-1.9903, -15.7497) to (-2.9806, -15.5926)
  arc A27 centre (-4.152, -12.8324) radius 0.8382 clockwise from (-3.894, -12.0349) to (-3.3398, -13.0395)
  arc A28 centre (0, 0) radius 12.6492 clockwise from (-3.894, -12.0349) to (-3.9286, -12.0236)
  arc A29 centre (-4.189, -12.8204) radius 0.8382 clockwise from (-4.9677, -12.5102) to (-3.9286, -12.0236)
  arc A30 centre (0, 0) radius 15.8749 clockwise from (-6.7598, -14.3638) to (-7.6531, -13.9084)
  arc A31 centre (-7.9142, -10.9213) radius 0.8382 clockwise from (-7.4224, -10.2425) to (-7.2058, -11.3693)
  arc A32 centre (0, 0) radius 12.6492 clockwise from (-7.4224, -10.2425) to (-7.4519, -10.2211)
  arc A33 centre (-7.9457, -10.8984) radius 0.8382 clockwise from (-8.5904, -10.3628) to (-7.4519, -10.2211)
  arc A34 centre (0, 0) radius 15.8749 clockwise from (-10.8676, -11.5719) to (-11.5764, -10.8628)
  arc A35 centre (-10.9017, -7.9411) radius 0.8382 clockwise from (-10.2242, -7.4476) to (-10.3664, -8.5861)
  arc A36 centre (0, 0) radius 12.6492 clockwise from (-10.2242, -7.4476) to (-10.2456, -7.4181)
  arc A37 centre (-10.9246, -7.9097) radius 0.8382 clockwise from (-11.3723, -7.201) to (-10.2456, -7.4181)
  arc A38 centre (0, 0) radius 15.8749 clockwise from (-13.9116, -7.6473) to (-14.3666, -6.7538)
  arc A39 centre (-12.8221, -4.1836) radius 0.8382 clockwise from (-12.0252, -3.9236) to (-12.5123, -4.9625)
  arc A40 centre (0, 0) radius 12.6492 clockwise from (-12.0252, -3.9236) to (-12.0365, -3.889)
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extrude "Extrude2" add sketch "Fill Top of Driven Gear" along normal blind 6.35
copy_paste "CutPaste1"
offset_faces "OffsetFaces1" distance -5.715
sketch "Y Restricttion Profile" plane through (0, 0, 37.465) normal (0, 0, -1) x axis (1, 0, 0)
  line L1 (10.4441, 8.6506) -> (10.3664, 8.5861)
  curve K1 (10.4441, 8.6506) -> (11.5764, 10.8628)
  curve K2 (10.8676, 11.5719) -> (8.655, 10.4405)
  line L2 (8.5904, 10.3628) -> (8.655, 10.4405)
  line L3 (7.2598, 11.4546) -> (7.2058, 11.3693)
  curve K3 (7.2598, 11.4546) -> (7.6531, 13.9084)
  curve K4 (6.7598, 14.3638) -> (5.0051, 12.604)
  line L4 (4.9677, 12.5102) -> (5.0051, 12.604)
  line L5 (3.3648, 13.1374) -> (3.3398, 13.0395)
  curve K5 (3.3648, 13.1374) -> (2.9806, 15.5926)
  curve K6 (1.9903, 15.7497) -> (0.8652, 13.5338)
  line L6 (0.8587, 13.433) -> (0.8652, 13.5338)
  line L7 (-0.8596, 13.5342) -> (-0.8531, 13.4334)
  curve K7 (-0.8596, 13.5342) -> (-1.9837, 15.7505)
  curve K8 (-2.9741, 15.5939) -> (-3.3593, 13.1388)
  line L8 (-3.3344, 13.0409) -> (-3.3593, 13.1388)
  line L9 (-4.9998, 12.6061) -> (-4.9625, 12.5123)
  curve K9 (-4.9998, 12.6061) -> (-6.7538, 14.3666)
  curve K10 (-7.6473, 13.9116) -> (-7.255, 11.4576)
  line L10 (-7.201, 11.3723) -> (-7.255, 11.4576)
  line L11 (-8.6506, 10.4441) -> (-8.5861, 10.3664)
  curve K11 (-8.6506, 10.4441) -> (-10.8628, 11.5764)
  curve K12 (-11.5719, 10.8676) -> (-10.4405, 8.655)
  line L12 (-10.3628, 8.5904) -> (-10.4405, 8.655)
  line L13 (-11.4546, 7.2598) -> (-11.3693, 7.2058)
  curve K13 (-11.4546, 7.2598) -> (-13.9084, 7.6531)
  curve K14 (-14.3638, 6.7598) -> (-12.604, 5.0051)
  line L14 (-12.5102, 4.9677) -> (-12.604, 5.0051)
  line L15 (-13.1374, 3.3648) -> (-13.0395, 3.3398)
  curve K15 (-13.1374, 3.3648) -> (-15.5926, 2.9806)
  curve K16 (-15.7497, 1.9903) -> (-13.5338, 0.8652)
  line L16 (-13.433, 0.8587) -> (-13.5338, 0.8652)
  line L17 (-13.5342, -0.8596) -> (-13.4334, -0.8531)
  curve K17 (-13.5342, -0.8596) -> (-15.7505, -1.9837)
  curve K18 (-15.5939, -2.9741) -> (-13.1388, -3.3593)
  line L18 (-13.0409, -3.3344) -> (-13.1388, -3.3593)
  line L19 (-12.6061, -4.9998) -> (-12.5123, -4.9625)
  curve K19 (-12.6061, -4.9998) -> (-14.3666, -6.7538)
  curve K20 (-13.9116, -7.6473) -> (-11.4576, -7.255)
  line L20 (-11.3723, -7.201) -> (-11.4576, -7.255)
  line L21 (-10.4441, -8.6506) -> (-10.3664, -8.5861)
  curve K21 (-10.4441, -8.6506) -> (-11.5764, -10.8628)
  curve K22 (-10.8676, -11.5719) -> (-8.655, -10.4405)
  line L22 (-8.5904, -10.3628) -> (-8.655, -10.4405)
  line L23 (-7.2598, -11.4546) -> (-7.2058, -11.3693)
  curve K23 (-7.2598, -11.4546) -> (-7.6531, -13.9084)
  curve K24 (-6.7598, -14.3638) -> (-5.0051, -12.604)
  line L24 (-4.9677, -12.5102) -> (-5.0051, -12.604)
  line L25 (-3.3648, -13.1374) -> (-3.3398, -13.0395)
  curve K25 (-3.3648, -13.1374) -> (-2.9806, -15.5926)
  curve K26 (-1.9903, -15.7497) -> (-0.8652, -13.5338)
  line L26 (-0.8587, -13.433) -> (-0.8652, -13.5338)
  line L27 (0.8596, -13.5342) -> (0.8531, -13.4334)
  curve K27 (0.8596, -13.5342) -> (1.9837, -15.7505)
  curve K28 (2.9741, -15.5939) -> (3.3593, -13.1388)
  line L28 (3.3344, -13.0409) -> (3.3593, -13.1388)
  line L29 (4.9998, -12.6061) -> (4.9625, -12.5123)
  curve K29 (4.9998, -12.6061) -> (6.7538, -14.3666)
  curve K30 (7.6473, -13.9116) -> (7.255, -11.4576)
  line L30 (7.201, -11.3723) -> (7.255, -11.4576)
  line L31 (8.6506, -10.4441) -> (8.5861, -10.3664)
  curve K31 (8.6506, -10.4441) -> (10.8628, -11.5764)
  curve K32 (11.5719, -10.8676) -> (10.4405, -8.655)
  line L32 (10.3628, -8.5904) -> (10.4405, -8.655)
  line L33 (11.4546, -7.2598) -> (11.3693, -7.2058)
  curve K33 (11.4546, -7.2598) -> (13.9084, -7.6531)
  curve K34 (14.3638, -6.7598) -> (12.604, -5.0051)
  line L34 (12.5102, -4.9677) -> (12.604, -5.0051)
  line L35 (13.1374, -3.3648) -> (13.0395, -3.3398)
  curve K35 (13.1374, -3.3648) -> (15.5926, -2.9806)
  curve K36 (15.7497, -1.9903) -> (13.5338, -0.8652)
  line L36 (13.433, -0.8587) -> (13.5338, -0.8652)
  line L37 (13.5342, 0.8596) -> (13.4334, 0.8531)
  curve K37 (13.5342, 0.8596) -> (15.7505, 1.9837)
  curve K38 (15.5939, 2.9741) -> (13.1388, 3.3593)
  line L38 (13.0409, 3.3344) -> (13.1388, 3.3593)
  line L39 (12.6061, 4.9998) -> (12.5123, 4.9625)
  curve K39 (12.6061, 4.9998) -> (14.3666, 6.7538)
  curve K40 (13.9116, 7.6473) -> (11.4576, 7.255)
  line L40 (11.3723, 7.201) -> (11.4576, 7.255)
  line L41 (0.0005, 17.78) -> (-0.0005, 17.78)
  arc A1 centre (10.9017, 7.9411) radius 0.8382 clockwise from (10.2242, 7.4476) to (10.3664, 8.5861)
  arc A2 centre (0, 0) radius 15.8749 clockwise from (10.8676, 11.5719) to (11.5764, 10.8628)
  arc A3 centre (7.9457, 10.8984) radius 0.8382 clockwise from (8.5904, 10.3628) to (7.4519, 10.2211)
  arc A4 centre (0, 0) radius 12.6492 clockwise from (7.4224, 10.2425) to (7.4519, 10.2211)
  arc A5 centre (7.9142, 10.9213) radius 0.8382 clockwise from (7.4224, 10.2425) to (7.2058, 11.3693)
  arc A6 centre (0, 0) radius 15.8749 clockwise from (6.7598, 14.3638) to (7.6531, 13.9084)
  arc A7 centre (4.189, 12.8204) radius 0.8382 clockwise from (4.9677, 12.5102) to (3.9286, 12.0236)
  arc A8 centre (0, 0) radius 12.6492 clockwise from (3.894, 12.0349) to (3.9286, 12.0236)
  arc A9 centre (4.152, 12.8324) radius 0.8382 clockwise from (3.894, 12.0349) to (3.3398, 13.0395)
  arc A10 centre (0, 0) radius 15.8749 clockwise from (1.9903, 15.7497) to (2.9806, 15.5926)
  arc A11 centre (0.0222, 13.4873) radius 0.8382 clockwise from (0.8587, 13.433) to (0.0209, 12.6491)
  arc A12 centre (0, 0) radius 12.6492 clockwise from (-0.0156, 12.6491) to (0.0209, 12.6491)
  arc A13 centre (-0.0166, 13.4873) radius 0.8382 clockwise from (-0.0156, 12.6491) to (-0.8531, 13.4334)
  arc A14 centre (0, 0) radius 15.8749 clockwise from (-2.9741, 15.5939) to (-1.9837, 15.7505)
  arc A15 centre (-4.1467, 12.8341) radius 0.8382 clockwise from (-3.3344, 13.0409) to (-3.889, 12.0365)
  arc A16 centre (0, 0) radius 12.6492 clockwise from (-3.9236, 12.0252) to (-3.889, 12.0365)
  arc A17 centre (-4.1836, 12.8221) radius 0.8382 clockwise from (-3.9236, 12.0252) to (-4.9625, 12.5123)
  arc A18 centre (0, 0) radius 15.8749 clockwise from (-7.6473, 13.9116) to (-6.7538, 14.3666)
  arc A19 centre (-7.9097, 10.9246) radius 0.8382 clockwise from (-7.201, 11.3723) to (-7.4181, 10.2456)
  arc A20 centre (0, 0) radius 12.6492 clockwise from (-7.4476, 10.2242) to (-7.4181, 10.2456)
  arc A21 centre (-7.9411, 10.9017) radius 0.8382 clockwise from (-7.4476, 10.2242) to (-8.5861, 10.3664)
  arc A22 centre (0, 0) radius 15.8749 clockwise from (-11.5719, 10.8676) to (-10.8628, 11.5764)
  arc A23 centre (-10.8984, 7.9457) radius 0.8382 clockwise from (-10.3628, 8.5904) to (-10.2211, 7.4519)
  arc A24 centre (0, 0) radius 12.6492 clockwise from (-10.2425, 7.4224) to (-10.2211, 7.4519)
  arc A25 centre (-10.9213, 7.9142) radius 0.8382 clockwise from (-10.2425, 7.4224) to (-11.3693, 7.2058)
  arc A26 centre (0, 0) radius 15.8749 clockwise from (-14.3638, 6.7598) to (-13.9084, 7.6531)
  arc A27 centre (-12.8204, 4.189) radius 0.8382 clockwise from (-12.5102, 4.9677) to (-12.0236, 3.9286)
  arc A28 centre (0, 0) radius 12.6492 clockwise from (-12.0349, 3.894) to (-12.0236, 3.9286)
  arc A29 centre (-12.8324, 4.152) radius 0.8382 clockwise from (-12.0349, 3.894) to (-13.0395, 3.3398)
  arc A30 centre (0, 0) radius 15.8749 clockwise from (-15.7497, 1.9903) to (-15.5926, 2.9806)
  arc A31 centre (-13.4873, 0.0222) radius 0.8382 clockwise from (-13.433, 0.8587) to (-12.6491, 0.0209)
  arc A32 centre (0, 0) radius 12.6492 clockwise from (-12.6491, -0.0156) to (-12.6491, 0.0209)
  arc A33 centre (-13.4873, -0.0166) radius 0.8382 clockwise from (-12.6491, -0.0156) to (-13.4334, -0.8531)
  arc A34 centre (0, 0) radius 15.8749 clockwise from (-15.5939, -2.9741) to (-15.7505, -1.9837)
  arc A35 centre (-12.8341, -4.1467) radius 0.8382 clockwise from (-13.0409, -3.3344) to (-12.0365, -3.889)
  arc A36 centre (0, 0) radius 12.6492 clockwise from (-12.0252, -3.9236) to (-12.0365, -3.889)
  arc A37 centre (-12.8221, -4.1836) radius 0.8382 clockwise from (-12.0252, -3.9236) to (-12.5123, -4.9625)
  arc A38 centre (0, 0) radius 15.8749 clockwise from (-13.9116, -7.6473) to (-14.3666, -6.7538)
  arc A39 centre (-10.9246, -7.9097) radius 0.8382 clockwise from (-11.3723, -7.201) to (-10.2456, -7.4181)
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  dimension "d426" = 3.175
extrude "Extrude1" add sketch "Y Restricttion Profile" blind -17.145 from offset 1.905
extrude "Extrude2" sketch "Y Restricttion Profile" blind 2.54
position "Position4"
component_insert "Component Insert3"
copy_paste "CutPaste3"
component_insert "Component Insert4"
component_insert "Component Insert5"
position "Position5"
copy_paste "CutPaste4"
copy_paste "CutPaste5"
component_insert "Component Insert6"
position "Position6"
sketch "Battery Housing  Profile" plane through (0, 0, 0) normal (0, 0, 1) x axis (-1, 0, 0)
  line L1 (-22.7722, -63.8838) -> (-22.7722, -42.9288)
  line L2 (-22.5182, -40.3888) -> (7.5808, -40.3888)
  line L3 (29.9328, -47.0563) -> (29.9328, -59.7563)
  line L4 (21.6778, -66.4238) -> (7.6062, -66.4238)
  line L5 (-22.7722, -40.3888) -> (-22.7722, -42.9288)
  line L6 (-22.7722, -40.3888) -> (-22.5182, -40.3888)
  line L7 (29.9328, -67.3083) -> (29.9328, -59.7563)
  line L8 (29.9328, -67.3083) -> (21.6778, -66.4238)
  line L9 (29.9328, -66.8048) -> (29.9328, -59.7563)
  line L10 (25.2338, -59.7563) -> (29.9328, -59.7563)
  line L11 (25.2338, -59.7563) -> (25.2338, -66.8048)
  line L12 (29.9328, -59.7563) -> (25.2338, -59.7563)
  line L13 (-22.7722, -66.4238) -> (7.6062, -66.4238)
  line L14 (-22.7722, -66.4238) -> (-22.7722, -63.8838)
  line L15 (21.6778, -40.3888) -> (7.5808, -40.3888)
  line L16 (-10.9827, -53.4063) -> (-22.7722, -53.4063)
  line L17 (29.9328, -39.5044) -> (21.6778, -40.3888)
  line L18 (29.9328, -39.5044) -> (29.9328, -47.0563)
  line L19 (-22.5182, -40.1348) -> (7.5808, -40.1348)
  line L20 (-23.0262, -40.1348) -> (-22.5182, -40.1348)
  line L21 (-23.0262, -40.1348) -> (-23.0262, -42.9288)
  line L22 (-23.0262, -63.8838) -> (-23.0262, -42.9288)
  line L23 (-23.0262, -66.6778) -> (-23.0262, -63.8838)
  line L24 (-23.0262, -66.6778) -> (7.6062, -66.6778)
  line L25 (21.6642, -66.6778) -> (7.6062, -66.6778)
  line L26 (30.1868, -67.591) -> (21.6642, -66.6778)
  line L27 (30.1868, -67.591) -> (30.1868, -59.7563)
  line L28 (30.1868, -47.0563) -> (30.1868, -59.7563)
  line L29 (30.1868, -39.2217) -> (30.1868, -47.0563)
  line L30 (30.1868, -39.2217) -> (21.6642, -40.1348)
  line L31 (21.6642, -40.1348) -> (7.5808, -40.1348)
  line L32 (32.7268, -36.395) -> (32.7268, -47.0563)
  line L33 (32.7268, -36.395) -> (21.5285, -37.5948)
  line L34 (21.5285, -37.5948) -> (7.5808, -37.5948)
  line L35 (-22.5182, -37.5948) -> (7.5808, -37.5948)
  line L36 (-25.5662, -37.5948) -> (-22.5182, -37.5948)
  line L37 (-25.5662, -37.5948) -> (-25.5662, -42.9288)
  line L38 (-25.5662, -63.8838) -> (-25.5662, -42.9288)
  line L39 (-25.5662, -69.2178) -> (-25.5662, -63.8838)
  line L40 (-25.5662, -69.2178) -> (7.6062, -69.2178)
  line L41 (21.5285, -69.2178) -> (7.6062, -69.2178)
  line L42 (32.7268, -70.4176) -> (21.5285, -69.2178)
  line L43 (32.7268, -70.4176) -> (32.7268, -59.7563)
  line L44 (32.7268, -47.0563) -> (32.7268, -59.7563)
  line L45 (-53.3641, 19.5) -> (-53.3641, 18.7139)
  line L46 (-36.5747, 18.7139) -> (-36.5747, 19.5)
  line L47 (-36.5747, -19.5) -> (-36.5747, -18.7139)
  line L48 (-53.3641, -18.7139) -> (-53.3641, -19.5)
  circle C1 centre (0, -84.1375) radius 1.804
  circle C2 centre (-36.5059, 75.8053) radius 1.804
  circle C3 centre (36.5059, 75.8053) radius 1.804
  circle C4 centre (-65.7813, -52.4589) radius 1.804
  circle C5 centre (65.7813, -52.4589) radius 1.804
  circle C6 centre (-82.028, 18.7224) radius 1.804
  circle C7 centre (82.028, 18.7224) radius 1.804
  circle C8 centre (0, 0) radius 88.9
  arc A1 centre (-44.9694, 0) radius 20.5105 clockwise from (-53.3641, -18.7139) to (-53.3641, 18.7139)
  arc A2 centre (-44.9694, 19.5) radius 8.3947 clockwise from (-53.3641, 19.5) to (-36.5747, 19.5)
  arc A3 centre (-44.9694, 0) radius 20.5105 clockwise from (-36.5747, 18.7139) to (-36.5747, -18.7139)
  arc A4 centre (-44.9694, -19.5) radius 8.3947 clockwise from (-36.5747, -19.5) to (-53.3641, -19.5)
  point P10 (-22.7722, -42.9288)
  point P18 (-22.7722, -42.9288)
  point P13 (-22.5182, -40.3888)
  point P19 (-22.5182, -40.3888)
  point P14 (29.9328, -59.7563)
  point P21 (29.9328, -59.7563)
  point P17 (21.6778, -66.4238)
  point P22 (21.6778, -66.4238)
  point P27 (25.2338, -66.8048)
  point P16 (7.6062, -66.4238)
  point P28 (7.6062, -66.4238)
  point P11 (-22.7722, -63.8838)
  point P29 (-22.7722, -63.8838)
  point P12 (7.5808, -40.3888)
  point P31 (7.5808, -40.3888)
  point P32 (-22.7722, -53.4063)
  point P36 (29.9328, -47.0563)
  point P34 (21.6778, -40.3888)
  point P23 (29.9328, -67.3083)
  point P35 (29.9328, -39.5044)
  coincident P10 P18
  parallel L1 L5
  coincident P13 P19
  perpendicular L5 L6
  coincident P14 P21
  parallel L3 L7
  coincident P17 P22
  coincident L8 P27
  coincident P16 P28
  parallel L4 L13
  coincident P11 P29
  perpendicular L13 L14
  coincident P12 P31
  parallel L2 L15
  midpoint L1 P32
  perpendicular L1 L16
  symmetric P21 L16 P36
  symmetric P22 L16 P34
  symmetric P23 L16 P35
  dimension "d190" = 2.794 (= "clearance + 0.1 in")
extrude "Extrude12" add sketch "Battery Housing  Profile" profile of L31 L30 L28 L27 L23 L26 L21 L29 L20 L25 L24 L22 L19 L44 L43 L39 L42 L38 L37 L32 L36 L34 L41 L40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 along normal blind 17.4625
joint "Assemble9" alignAngle 0 alignOffsetX -0.3175 alignOffsetY 0 alignOffsetZ 0
sketch "Battery Housing  Wire Exit" plane through (0, 0, 17.4625) normal (0, 0, 1) x axis (-1, 0, 0)
  line L1 (21.6642, -40.1348) -> (-23.0262, -40.1348)
  line L2 (30.1868, -39.2217) -> (21.6642, -40.1348)
  line L3 (30.1868, -67.591) -> (30.1868, -39.2217)
  line L4 (21.6642, -66.6778) -> (30.1868, -67.591)
  line L5 (-23.0262, -66.6778) -> (21.6642, -66.6778)
  line L6 (-23.0262, -40.1348) -> (-23.0262, -66.6778)
  line L7 (21.5285, -69.2178) -> (-25.5662, -69.2178)
  line L8 (32.7268, -70.4176) -> (21.5285, -69.2178)
  line L9 (32.7268, -36.395) -> (32.7268, -70.4176)
  line L10 (21.5285, -37.5948) -> (32.7268, -36.395)
  line L11 (-25.5662, -37.5948) -> (21.5285, -37.5948)
  line L12 (-25.5662, -69.2178) -> (-25.5662, -37.5948)
  line L13 (25.1068, -58.1688) -> (32.7268, -58.1688)
  line L14 (25.1068, -48.6438) -> (25.1068, -58.1688)
  line L15 (32.7268, -48.6438) -> (25.1068, -48.6438)
  line L16 (32.7268, -58.1688) -> (32.7268, -48.6438)
  line L17 (32.7268, -53.4063) -> (25.1068, -53.4063)
  point P14 (32.7268, -58.1688)
  point P18 (25.1068, -53.4063)
  point P19 (32.7268, -53.4063)
  point P15 (25.1068, -58.1688)
  point P16 (25.1068, -48.6438)
  horizontal L13
  vertical L14
  horizontal L15
  vertical L16
  coincident L9 P14
  midpoint L14 P18
  midpoint L9 P19
  horizontal L17
  dimension "d199" distance P15 P16 = 9.525 (= "( 3 / 8 ) * 1 in")
  dimension "d200" distance L3 L14 = 5.08
extrude "Extrude13" add sketch "Battery Housing  Wire Exit" profile of L1 L2 L3 L4 L5 L6 L7 L8 L9 L10 L11 L12 L13 L14 L15 L16 along normal blind 2.54
sketch "Battery Housing  Material Cut" plane through (0, 0, 20.0025) normal (0, 0, 1) x axis (-1, 0, 0)
  line L1 (25.1068, -48.6438) -> (25.1068, -58.1688)
  line L2 (30.1868, -48.6438) -> (25.1068, -48.6438)
  line L3 (30.1868, -58.1688) -> (30.1868, -48.6438)
  line L4 (25.1068, -58.1688) -> (30.1868, -58.1688)
  line L5 (21.5285, -37.5948) -> (32.7268, -36.395)
  line L6 (-25.5662, -37.5948) -> (21.5285, -37.5948)
  line L7 (-25.5662, -69.2178) -> (-25.5662, -37.5948)
  line L8 (21.5285, -69.2178) -> (-25.5662, -69.2178)
  line L9 (32.7268, -70.4176) -> (21.5285, -69.2178)
  line L10 (32.7268, -36.395) -> (32.7268, -70.4176)
  line L11 (21.5285, -69.2178) -> (21.5285, -37.5948)
  line L12 (20.32, -53.4063) -> (21.5285, -53.4063)
  line L13 (-25.5662, -53.4063) -> (20.32, -53.4063)
  line L14 (21.5285, -59.6928) -> (-16.0412, -59.6928)
  line L15 (-16.0412, -47.1198) -> (21.5285, -47.1198)
  line L16 (-16.0412, -59.6928) -> (-16.0412, -47.1198)
  point P7 (21.5285, -37.5948)
  point P12 (21.5285, -37.5948)
  point P10 (21.5285, -69.2178)
  point P13 (21.5285, -69.2178)
  point P14 (21.5285, -53.4063)
  point P16 (-25.5662, -53.4063)
  point P17 (-2.6231, -53.4063)
  point P20 (21.5285, -47.1198)
  point P21 (21.5285, -59.6928)
  coincident P7 P12
  coincident P10 P13
  midpoint L11 P14
  perpendicular L11 L12
  midpoint L7 P16
  midpoint L13 P17
  coincident L11 P20
  coincident L11 P21
extrude "Extrude14" cut sketch "Battery Housing  Material Cut" profile of L11 L16 L15 L14 against normal blind 7.62
extrude "Extrude15" cut of existing geometry blind -35.56
fillet "Fillet3" radius 1.27
chamfer "Chamfer5" distance 1.27
sketch "Switch Housing Profile" plane through (0, 0, 0) normal (0, 0, 1) x axis (-1, 0, 0)
  line L1 (-24.2962, -70.4878) -> (21.4607, -70.4878)
  line L2 (-26.8362, -38.8648) -> (-26.8362, -67.9478)
  line L3 (21.4607, -36.3248) -> (-24.2962, -36.3248)
  line L4 (31.1862, -35.2828) -> (21.4607, -36.3248)
  line L5 (33.9968, -69.0043) -> (33.9968, -37.8084)
  line L6 (21.4607, -70.4878) -> (31.1862, -71.5298)
  line L7 (11.0236, 56.6547) -> (-11.0236, 56.6547)
  line L8 (-11.0236, 70.3453) -> (11.0236, 70.3453)
  line L9 (11.0236, 70.3453) -> (11.0236, 56.6547)
  line L10 (-11.0236, 56.6547) -> (-11.0236, 70.3453)
  line L11 (11.2776, 56.4007) -> (-11.2776, 56.4007)
  line L12 (11.2776, 70.5993) -> (11.2776, 56.4007)
  line L13 (-11.2776, 70.5993) -> (11.2776, 70.5993)
  line L14 (-11.2776, 56.4007) -> (-11.2776, 70.5993)
  line L15 (13.8176, 73.1393) -> (13.8176, 53.8607)
  line L16 (-13.8176, 73.1393) -> (13.8176, 73.1393)
  line L17 (-13.8176, 53.8607) -> (-13.8176, 73.1393)
  line L18 (13.8176, 53.8607) -> (-13.8176, 53.8607)
  line L19 (-53.3641, 19.5) -> (-53.3641, 18.7139)
  line L20 (-36.5747, 18.7139) -> (-36.5747, 19.5)
  line L21 (-36.5747, -19.5) -> (-36.5747, -18.7139)
  line L22 (-53.3641, -18.7139) -> (-53.3641, -19.5)
  circle C1 centre (0, -84.1375) radius 1.804
  circle C2 centre (-36.5059, 75.8053) radius 1.804
  circle C3 centre (36.5059, 75.8053) radius 1.804
  circle C4 centre (-65.7813, -52.4589) radius 1.804
  circle C5 centre (65.7813, -52.4589) radius 1.804
  circle C6 centre (-82.028, 18.7224) radius 1.804
  circle C7 centre (82.028, 18.7224) radius 1.804
  circle C8 centre (0, 0) radius 88.9
  arc A1 centre (-24.2962, -67.9478) radius 2.54 clockwise from (-24.2962, -70.4878) to (-26.8362, -67.9478)
  arc A2 centre (-24.2962, -38.8648) radius 2.54 clockwise from (-26.8362, -38.8648) to (-24.2962, -36.3248)
  arc A3 centre (31.4568, -37.8084) radius 2.54 clockwise from (31.1862, -35.2828) to (33.9968, -37.8084)
  arc A4 centre (31.4568, -69.0043) radius 2.54 clockwise from (33.9968, -69.0043) to (31.1862, -71.5298)
  arc A5 centre (-44.9694, 0) radius 20.5105 clockwise from (-53.3641, -18.7139) to (-53.3641, 18.7139)
  arc A6 centre (-44.9694, 19.5) radius 8.3947 clockwise from (-53.3641, 19.5) to (-36.5747, 19.5)
  arc A7 centre (-44.9694, 0) radius 20.5105 clockwise from (-36.5747, 18.7139) to (-36.5747, -18.7139)
  arc A8 centre (-44.9694, -19.5) radius 8.3947 clockwise from (-36.5747, -19.5) to (-53.3641, -19.5)
  dimension "d209" = 0.254 (= "clearance")
  dimension "d210" = 2.794 (= "clearance + 0.1 in")
extrude "Extrude16" add sketch "Switch Housing Profile" profile of L14 L12 L13 L11 L17 L18 L16 L15 along normal blind 12.7 taper 0.376
copy_paste "CutPaste6"
extrude "Extrude17" cut of existing geometry blind -17.78
joint "Assemble11" alignAngle -90 alignOffsetX 3.175 alignOffsetY 0 alignOffsetZ 0
extrude "Extrude19" of existing geometry blind 7.62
